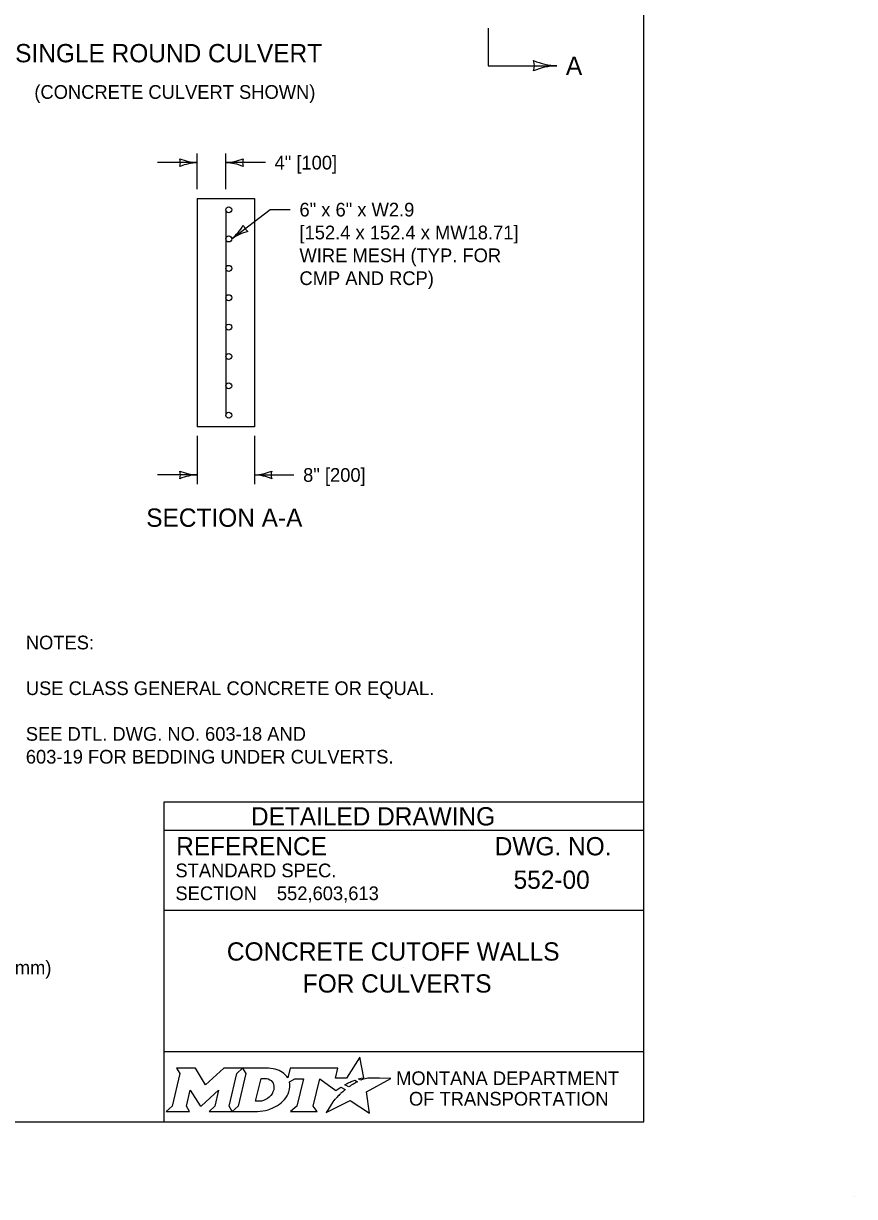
# Model space of a CAD drawing. Extents: x 49988.5 to 50021, y 49987.6 to 50011.4.
# Drawn here: x 50005.9 to 50009.54, y 49999.74 to 50004.87 of the extents above; entities that cross this region are included whole.
import ezdxf

# ---------------------------------------------------------------- set-up
doc = ezdxf.new("R2010")
doc.units = 0
for name, color, linetype in [('Level 1', 7, 'Continuous'), ('Level 2', 7, 'Continuous'), ('Level 3', 7, 'Continuous'), ('Level 6', 7, 'Continuous')]:
    doc.layers.add(name, color=color, linetype=linetype)

msp = doc.modelspace()

# ---------------------------------------------------------------- linework, layer by layer
at = {"layer": 'Level 1'}
for p, q in [((50006.6603, 50004.1048), (50006.6603, 50003.1048)), ((50006.6603, 50004.1048), (50006.9103, 50004.1048)), ((50006.9103, 50004.1048), (50006.9103, 50003.1048)), ((50006.7853, 50004.0548), (50006.7853, 50003.1548)), ((50006.9103, 50003.1048), (50006.6603, 50003.1048)), ((50008.2507, 50001.1223), (50008.2507, 50001.1223)), ((50007.0089, 50001.0629), (50007.0089, 50001.0629)), ((50007.5646, 50000.7383), (50007.5646, 50000.7383)), ((50009.5374, 49999.7356), (50009.5374, 49999.7356))]:
    msp.add_line(p, q, dxfattribs=at)
msp.add_lwpolyline([(50008.6146, 50011.2628), (50000.3356, 50011.2628), (50000.3356, 50000.0624), (50008.6146, 50000.0624)], close=True, dxfattribs=at)
for centre in [(50006.7984, 50004.0545), (50006.7984, 50003.9269), (50006.7984, 50003.7983), (50006.7984, 50003.6697), (50006.7984, 50003.5412), (50006.7984, 50003.4126), (50006.7984, 50003.284), (50006.7984, 50003.1555)]:
    msp.add_circle(centre, 0.0131, dxfattribs=at)
at = {"layer": 'Level 2'}
for p, q in [((50008.6146, 50001.4624), (50006.5146, 50001.4624)), ((50006.5146, 50001.4624), (50006.5146, 50000.0624)), ((50008.6146, 50001.3374), (50006.5146, 50001.3374)), ((50008.2507, 50001.1223), (50008.2507, 50001.1223)), ((50007.0089, 50001.0629), (50007.0089, 50001.0629)), ((50008.6146, 50000.9874), (50006.5146, 50000.9874)), ((50007.5646, 50000.7383), (50007.5646, 50000.7383)), ((50008.6146, 50000.3693), (50006.5146, 50000.3693))]:
    msp.add_line(p, q, dxfattribs=at)
for points in [[(50007.3771, 50000.2447), (50007.3668, 50000.2503), (50007.3784, 50000.2531), (50007.39, 50000.2551), (50007.3726, 50000.3452), (50007.3131, 50000.2539), (50007.2658, 50000.2532), (50007.2761, 50000.2973), (50007.0669, 50000.2974), (50007.0568, 50000.2549), (50007.051, 50000.2632)], [(50006.5701, 50000.2974), (50006.5842, 50000.274), (50006.5507, 50000.1307), (50006.525, 50000.1082), (50006.6266, 50000.1082), (50006.6131, 50000.131), (50006.6293, 50000.2011), (50006.673, 50000.1321), (50006.6783, 50000.1321), (50006.7534, 50000.2016), (50006.737, 50000.1305), (50006.7123, 50000.1085), (50006.8139, 50000.1085), (50006.8001, 50000.1318), (50006.8333, 50000.2742)], [(50006.8333, 50000.2742), (50006.8586, 50000.2974), (50006.7762, 50000.2974), (50006.6966, 50000.2244), (50006.6521, 50000.2971), (50006.5701, 50000.2974)], [(50006.9722, 50000.2974), (50006.8586, 50000.2974), (50006.8733, 50000.2745), (50006.8394, 50000.1307), (50006.8139, 50000.1085), (50006.9245, 50000.1085)], [(50006.9962, 50000.2107), (50006.995, 50000.2026), (50006.9918, 50000.1933), (50006.9876, 50000.1851), (50006.982, 50000.1776), (50006.9755, 50000.1707), (50006.9676, 50000.1644), (50006.9593, 50000.1597), (50006.9502, 50000.1558), (50006.9411, 50000.1535), (50006.9319, 50000.1526), (50006.916, 50000.1526), (50006.9396, 50000.2526), (50006.9556, 50000.2526), (50006.9632, 50000.252), (50006.9708, 50000.2501), (50006.9774, 50000.2471), (50006.9835, 50000.2429), (50006.9883, 50000.2379), (50006.992, 50000.2319), (50006.9947, 50000.2257), (50006.9963, 50000.2183), (50006.9963, 50000.2153), (50006.9962, 50000.2107)], [(50007.0636, 50000.2383), (50007.0882, 50000.2514), (50007.1251, 50000.2514), (50007.0965, 50000.1309), (50007.069, 50000.1082), (50007.1852, 50000.1082), (50007.1682, 50000.1311), (50007.1964, 50000.2513), (50007.2677, 50000.1996), (50007.2888, 50000.2147), (50007.3085, 50000.2038)], [(50007.2527, 50000.1479), (50007.2374, 50000.1235), (50007.2327, 50000.116), (50007.2269, 50000.1074), (50007.2246, 50000.1031), (50007.3299, 50000.1562), (50007.4138, 50000.1011), (50007.4007, 50000.1938), (50007.5076, 50000.2522), (50007.4583, 50000.253), (50007.4282, 50000.2534), (50007.4074, 50000.2537), (50007.4006, 50000.2522), (50007.3957, 50000.251), (50007.3873, 50000.2487), (50007.3771, 50000.2447)], [(50007.3267, 50000.2171), (50007.3243, 50000.2154), (50007.306, 50000.225), (50007.3163, 50000.2307), (50007.3204, 50000.2329), (50007.329, 50000.2369), (50007.3347, 50000.2395), (50007.3426, 50000.2425), (50007.3499, 50000.2452), (50007.3617, 50000.2378), (50007.3577, 50000.2357), (50007.3531, 50000.2332), (50007.3489, 50000.231), (50007.3439, 50000.2281), (50007.342, 50000.227), (50007.3393, 50000.2254), (50007.3368, 50000.224), (50007.3345, 50000.2224), (50007.3319, 50000.2206), (50007.3292, 50000.2188), (50007.3267, 50000.2171)], [(50006.9702, 50000.1158), (50006.9786, 50000.1184), (50006.9916, 50000.1238), (50007.012, 50000.1348)], [(50007.2666, 50000.164), (50007.2666, 50000.164)]]:
    msp.add_lwpolyline(points, dxfattribs=at)
for centre, radius, start, end in [((50006.9953, 50000.219), 0.0709, 339.5329, 15.8582), ((50006.9513, 50000.2363), 0.1183, 300.9103, 339.1383)]:
    msp.add_arc(centre, radius, start, end, dxfattribs=at)
for centre, major_axis, ratio, start_param, end_param in [((50006.9701, 50000.25), (0.0834, -0.0037), 0.568097, 0.61298, 1.570796), ((50007.0257, 50000.2573), (0.0361, -0.0295), 0.469099, 1.225588, 1.570796), ((50007.2764, 50000.1742), (-0.0098, -0.0102), 0.016458, 3.141593, 6.279097), ((50007.2974, 50000.1941), (-0.0112, -0.0097), 0.021651, 3.157348, 6.283185), ((50007.2597, 50000.1559), (-0.00694, -0.00806), 0.008222, 0, 3.137361), ((50006.9248, 50000.2568), (0, 0.1484), 0.987302, 3.139398, 3.456847)]:
    msp.add_ellipse(centre, major_axis=major_axis, ratio=ratio, start_param=start_param, end_param=end_param, dxfattribs=at)
at = {"layer": 'Level 3'}
for p, q in [((50006.6603, 50004.1448), (50006.6603, 50004.301)), ((50006.7853, 50004.1448), (50006.7853, 50004.301)), ((50006.6603, 50004.261), (50006.4869, 50004.261)), ((50006.9587, 50004.261), (50006.7853, 50004.261)), ((50006.8115, 50003.9274), (50006.9795, 50004.0553)), ((50006.9795, 50004.0553), (50007.0678, 50004.0553)), ((50006.6603, 50003.0648), (50006.6603, 50002.8543)), ((50006.9103, 50003.0648), (50006.9103, 50002.8542)), ((50006.6603, 50002.8943), (50006.4869, 50002.8943)), ((50006.9103, 50002.8942), (50007.0838, 50002.894))]:
    msp.add_line(p, q, dxfattribs=at)
for centre, radius, start, end in [((50006.6695, 50004.4832), 0.2223, 247.456, 267.6395), ((50006.5321, 50004.261), 0.0548, 342.1388, 17.8612), ((50006.6718, 50004.0283), 0.233, 92.8273, 112.0772), ((50006.7738, 50004.4937), 0.233, 272.8273, 292.0772), ((50006.7761, 50004.0389), 0.2223, 67.456, 87.6395), ((50006.9135, 50004.261), 0.0548, 162.1388, 197.8612), ((50006.6614, 50004.1056), 0.233, 310.1124, 329.3623), ((50006.9135, 50004.0051), 0.0548, 199.4239, 235.1463), ((50006.9388, 50003.7451), 0.2223, 104.7411, 124.9246), ((50006.6695, 50003.1165), 0.2223, 247.456, 267.6395), ((50006.5321, 50002.8943), 0.0548, 342.1388, 17.8612), ((50006.8988, 50003.1269), 0.233, 272.8273, 292.0772), ((50007.0385, 50002.8942), 0.0548, 162.1388, 197.8612), ((50006.6718, 50002.6616), 0.233, 92.8273, 112.0772), ((50006.9011, 50002.672), 0.2223, 67.456, 87.6395)]:
    msp.add_arc(centre, radius, start, end, dxfattribs=at)
at = {"layer": 'Level 6'}
for p, q in [((50007.934, 50004.8498), (50007.934, 50004.6852)), ((50007.934, 50004.6852), (50008.234, 50004.6852))]:
    msp.add_line(p, q, dxfattribs=at)
for centre, radius, start, end in [((50008.2462, 50004.9814), 0.2964, 247.456, 267.6395), ((50008.063, 50004.6852), 0.073, 342.1388, 17.8612), ((50008.2493, 50004.375), 0.3107, 92.8273, 112.0772)]:
    msp.add_arc(centre, radius, start, end, dxfattribs=at)

# ---------------------------------------------------------------- texts
at = {"layer": 'Level 2'}
for s, height, p in [('SINGLE ROUND CULVERT', 0.08, (50005.8635, 50004.7003)), ('A', 0.08, (50008.274, 50004.6452)), ('(CONCRETE CULVERT SHOWN)', 0.06, (50005.9473, 50004.5403)), ('4" [100]', 0.06, (50006.9987, 50004.231)), ('6" x 6" x W2.9 ', 0.06, (50007.1078, 50004.0253)), ('[152.4 x 152.4 x MW18.71]', 0.06, (50007.1078, 50003.9253)), ('WIRE MESH (TYP. FOR', 0.06, (50007.1078, 50003.8253)), ('CMP AND RCP)', 0.06, (50007.1078, 50003.7253)), ('8" [200]', 0.06, (50007.1238, 50002.864)), ('SECTION A-A', 0.08, (50006.4371, 50002.6671)), ('NOTES:', 0.06, (50005.91, 50002.1306)), ('USE CLASS GENERAL CONCRETE OR EQUAL.', 0.06, (50005.91, 50001.9306)), ('SEE DTL. DWG. NO. 603-18 AND', 0.06, (50005.91, 50001.7306)), ('603-19 FOR BEDDING UNDER CULVERTS.', 0.06, (50005.91, 50001.6306)), ('DETAILED DRAWING', 0.0799, (50006.8956, 50001.3599)), ('REFERENCE', 0.08, (50006.5682, 50001.229)), ('DWG. NO.', 0.08, (50007.9624, 50001.229)), ('STANDARD SPEC.', 0.06, (50006.5649, 50001.133)), ('SECTION', 0.06, (50006.5649, 50001.033)), ('552,603,613', 0.06, (50007.0089, 50001.0329)), ('CONCRETE CUTOFF WALLS', 0.08, (50006.79, 50000.7683)), ('METRIC AND ARE IN MILLIMETERS (mm) ', 0.06, (50004.4665, 50000.7076)), ('FOR CULVERTS', 0.08, (50007.1224, 50000.6283)), ('MONTANA DEPARTMENT', 0.06, (50007.5308, 50000.2236)), ('OF TRANSPORTATION', 0.06, (50007.587, 50000.1336))]:
    msp.add_text(s, height=height, dxfattribs=at).set_placement(p)
msp.add_text('552-00', height=0.08, rotation=359.9, dxfattribs=at).set_placement((50008.045, 50001.0827))

doc.saveas('drawing.dxf')
